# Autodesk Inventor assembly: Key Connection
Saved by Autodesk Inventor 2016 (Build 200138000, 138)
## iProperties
Created: 2015-03
Part Number: Key Connection
Document SubType Name: Assembly
Designer: Uglješa
ClientObjectVersion: 1
Author: Uglješa
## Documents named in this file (1)
- C:\Users\Ugljesa\Desktop\Turbokompr\Assembly1\Design Accelerator\Key Connection9.iam
